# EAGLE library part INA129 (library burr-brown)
Instrumentation Amplifiers Precision, Low Power
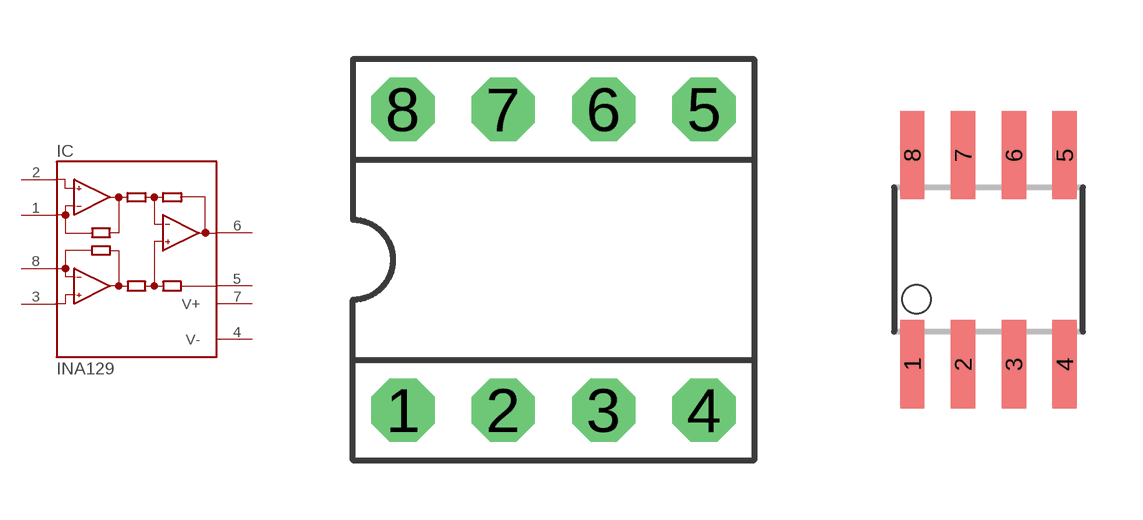
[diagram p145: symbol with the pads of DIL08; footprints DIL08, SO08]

Designator prefix IC

## INA129P (MF: TEXAS INSTRUMENTS; MPN: INA129P; OC_FARNELL: 1212414; OC_NEWARK: 74C9786)  [DIL08]
1  RG  pas
2  -IN  in
3  +IN  in
4  V-  pwr
5  REF  pas
6  OUT  out
7  V+  pwr
8  RG  pas

## INA129U (MF: TEXAS INSTRUMENTS; MPN: INA129U; OC_FARNELL: 1212415; OC_NEWARK: 35C1732)  [SO08]
Pads as for DIL08

## Footprint DIL08 (pad centres in mm)
Dual In Line
drill 0.813 pad 1.6 octagon: 1 -3.81,-3.81; 2 -1.27,-3.81; 3 1.27,-3.81; 4 3.81,-3.81; 5 3.81,3.81; 6 1.27,3.81; 7 -1.27,3.81; 8 -3.81,3.81

## Footprint SO08 (pad centres in mm)
Small Outline Package
smd 0.61 x 2.21: 1 -1.905,-2.616; 2 -0.635,-2.616; 3 0.635,-2.616; 4 1.905,-2.616; 5 1.905,2.616; 6 0.635,2.616; 7 -0.635,2.616; 8 -1.905,2.616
